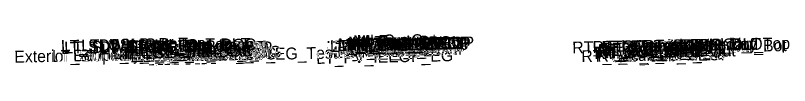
# Model space of a CAD drawing. Extents: x 118 to 4243, y 0 to 9511.
# Drawn here: x 129.3 to 260.3, y 4999.9 to 5005.5 of the extents above; entities that cross this region are included whole.
import ezdxf

# ---------------------------------------------------------------- set-up
doc = ezdxf.new("R2010")
doc.units = 0
doc.layers.add('Scratch_Level_0', color=7, linetype='Continuous')

msp = doc.modelspace()

# ---------------------------------------------------------------- texts
at = {"layer": 'Scratch_Level_0'}
for s, p in [('LT_SDWK_Out_Top', (137.01, 5002.42)), ('LT_Sub_Trench_Out_DLT', (137.57, 5002.17)), ('LT_CSLP_Pnt', (140.44, 5002.5)), ('LT_PV1_IEEOP', (182.54, 5002.41)), ('LT_PV1_PGL', (183.8, 5002.56)), ('MI_Face In', (183.92, 5002.73)), ('RT_PV2_OEEOP', (185.28, 5002.5)), ('MI_Top In', (185.63, 5003)), ('RT_PV1_OEEOP', (185.85, 5002.63)), ('RT_PV2_IEEOP', (185.93, 5002.51)), ('MI_Face Out', (186.28, 5002.93)), ('MI_Top Out', (186.49, 5003.2)), ('RT_PV1_IEEOP', (186.49, 5002.65)), ('RT_PV2_PGL1', (186.86, 5002.53)), ('MI_Crown', (187.09, 5003.27)), ('RT_PV2_PGL', (187.19, 5002.54)), ('MI_Bot Out', (187.28, 5002.79)), ('RT_PV1_PGL', (187.75, 5002.8)), ('RT_Sub_Trench_Out_DLT', (223.56, 5002.17)), ('Exterior Boundary', (233.41, 5002.38)), ('RT_SDWK_Out_Top', (235.46, 5002.42)), ('RT_Shld_O', (241.81, 5002.54)), ('LT_SDWK_Out_Bot', (137.04, 5002.09)), ('LT_SDWK_In_Top', (143.63, 5002.35)), ('LT_SDWK_In_Bot', (143.66, 5002.02)), ('LT_CG1_Shelf_Out', (145.82, 5001.22)), ('LT_CG_Top_Face', (147.53, 5002.25)), ('LT_CG_Top_BOC', (148.05, 5002.27)), ('LT_CG_Bot_BOC', (148.09, 5001.26)), ('LT_CG_Top_Gut', (148.51, 5001.77)), ('LT_PV_OEEOP_EG', (149.82, 5000.98)), ('LT_PV2_OEEOP', (151.58, 5001.66)), ('LT_PV3_OEEOP', (151.58, 5001.33)), ('LT_PV1_OEEOP', (152.15, 5001.8)), ('LT_CG_Bot_IE', (152.19, 5001.34)), ('LT_PV2_OEOT', (152.45, 5001.68)), ('LT_PV3_OEOT', (152.45, 5001.35)), ('LT_PV1_OEOT', (153.01, 5001.94)), ('LT_PV2_IEEOP', (181.97, 5002.27)), ('LT_PV3_IEEOP', (181.97, 5001.94)), ('LT_PV2_PGL1', (182.9, 5002.29)), ('LT_PV3_PGL1', (182.9, 5001.96)), ('LT_PV2_PGL', (183.23, 5002.3)), ('LT_PV3_PGL', (183.23, 5001.96)), ('LT_PV4_PGL', (183.23, 5001.38)), ('RT_Sub_OEEOP', (185.19, 5001.58)), ('RT_PV3_OEEOP', (185.28, 5002.16)), ('RT_PV3_PGL1', (186.86, 5002.2)), ('RT_PV4_PGL', (187.19, 5001.62)), ('RT_CG_Top_Face', (226.99, 5002.25)), ('RT_CG1_Shelf_Out', (227.28, 5001.21)), ('RT_CG_Bot_IE', (227.64, 5001.34)), ('RT_PV2_OEOT', (227.9, 5001.68)), ('RT_PV3_OEOT', (227.9, 5001.35)), ('RT_CG_Top_Gut', (227.96, 5001.77)), ('RT_PV1_OEOT', (228.46, 5001.94)), ('RT_CG_Top_BOC', (228.51, 5002.27)), ('RT_CG_Bot_BOC', (228.54, 5001.26)), ('RT_SDWK_In_Top', (232.08, 5002.35)), ('RT_SDWK_In_Bot', (232.11, 5002.02)), ('RT_SDWK_Out_Bot', (235.49, 5002.09)), ('Exterior Boundary', (129.12, 5000.62)), ('LT_Slope_Fill', (135.5, 5000.74)), ('LT_PV_Sub_Tie_Out', (147.23, 5000.93)), ('LT_Sub_OEOP', (148.79, 5000.69)), ('LT_Sub_OEOT_CG', (149.64, 5000.71)), ('LT_Sub_OEEOP', (151.48, 5000.75)), ('LT_Sub_OEOT', (152.35, 5000.76)), ('LT_PV_EG_TestPt', (163.56, 5000.92)), ('LT_PV_IEEOP_EG', (180.21, 5000.41)), ('RT_Sub_OEOT_CG', (225.1, 5000.71)), ('RT_Sub_OEOT', (227.8, 5000.76)), ('RT_Sub_OEOP', (231.43, 5000.69))]:
    msp.add_text(s, height=2, rotation=1.1458, dxfattribs=at).set_placement(p)

doc.saveas('drawing.dxf')
